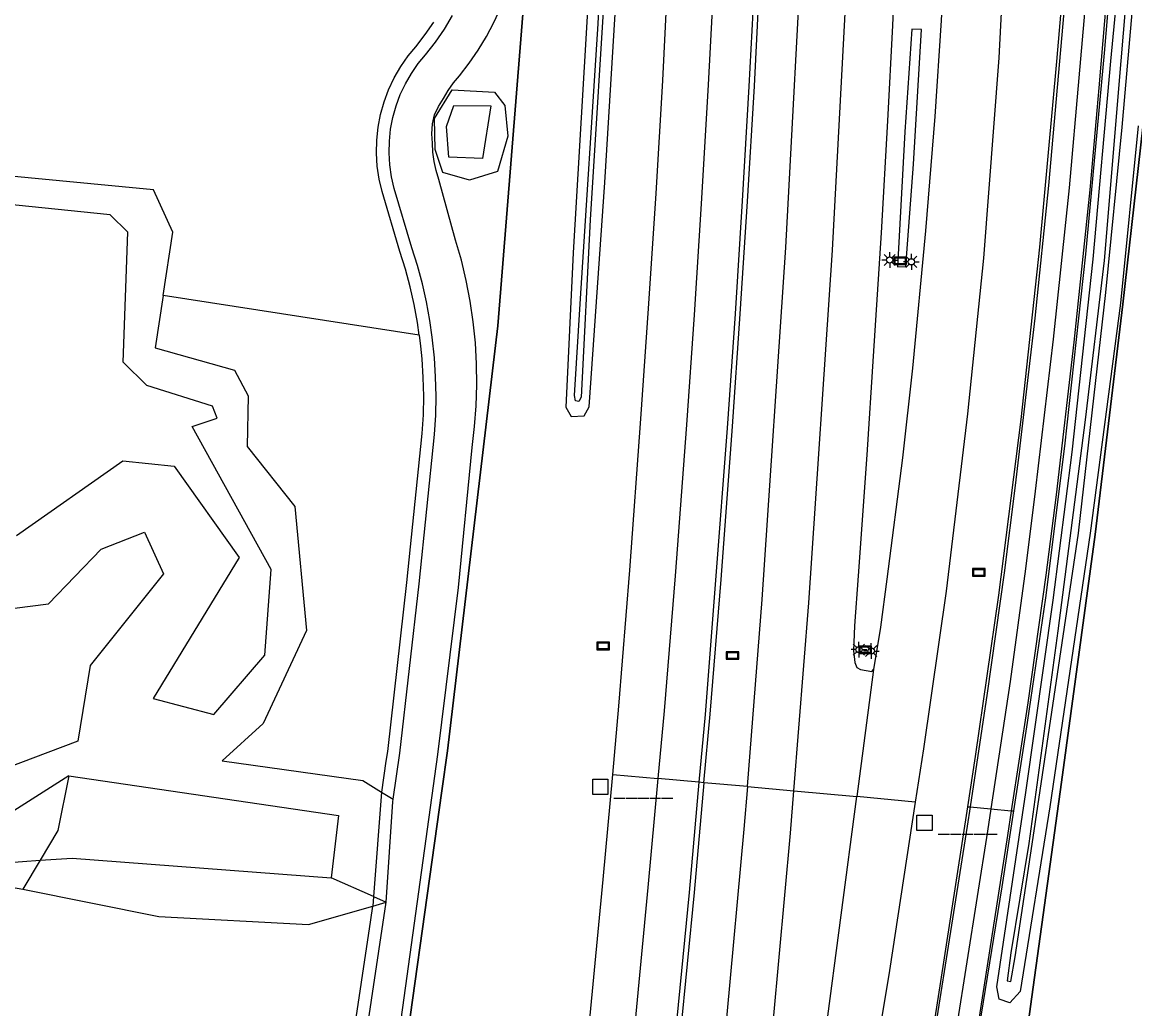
# Model space of a CAD drawing. Extents: x 124000 to 129000, y 395500 to 397503.
# Drawn here: x 124745.4 to 124833.3, y 397082 to 397160 of the extents above; entities that cross this region are included whole.
import ezdxf

# ---------------------------------------------------------------- set-up
doc = ezdxf.new("R2010")
doc.units = 0
for name, color, linetype in [('gg-afsc-hekwerk', 7, 'Continuous'), ('gg-afsc-lijn draadraster', 7, 'Continuous'), ('gg-knt-BGT kruinlijn', 7, 'Continuous'), ('gt-symb-bord', 7, 'Continuous'), ('gt-symb-hm paal', 7, 'Continuous'), ('gt-symb-lichtmast', 7, 'Continuous'), ('gx-grn-maaiveld', 7, 'Continuous'), ('gx-knt-lijn weginrichtingselement', 7, 'Continuous')]:
    doc.layers.add(name, color=color, linetype=linetype)

# ---------------------------------------------------------------- blocks, each defined once
blk = doc.blocks.new('gt0-LMAST')
at = {"layer": 'gt-symb-lichtmast'}
for p, q in [((-0.182, 0.173), (-0.447, 0.438)), ((-0.005, 0.246), (-0.005, 0.621)), ((0.172, 0.173), (0.437, 0.438)), ((-0.255, -0.004), (-0.63, -0.004)), ((-0.182, -0.181), (-0.447, -0.446)), ((-0.005, -0.254), (-0.005, -0.629)), ((0.437, -0.446), (0.172, -0.181)), ((0.245, -0.004), (0.62, -0.004))]:
    blk.add_line(p, q, dxfattribs=at)
blk.add_circle((-0.005, -0.004), 0.25, dxfattribs=at)
blk = doc.blocks.new('gt0-BORD')
at = {"layer": 'gt-symb-bord'}
blk.add_lwpolyline([(-0.5, 0.295), (-0.5, -0.295), (0.5, -0.295), (0.5, 0.295), (-0.5, 0.295)], dxfattribs=at)
blk.add_lwpolyline([(-0.417, -0.212), (0.417, -0.212), (0.417, 0.212), (-0.417, 0.212)], close=True, dxfattribs=at)
blk = doc.blocks.new('gt0-HMpaal')
at = {"layer": 'gt-symb-hm paal'}
blk.add_lwpolyline([(-0.6, 0.6), (0.6, 0.6), (0.6, -0.6), (-0.6, -0.6)], close=True, dxfattribs=at)

msp = doc.modelspace()

# ---------------------------------------------------------------- linework, layer by layer
at = {"layer": 'gg-afsc-hekwerk'}
msp.add_lwpolyline([(124774.888, 397073.073), (124778.544, 397099.23), (124778.986, 397102.392), (124782.98, 397135.974), (124785.856, 397172.14), (124786.014, 397176.607), (124786.937, 397202.711), (124786.926, 397202.713)], dxfattribs=at)
at = {"layer": 'gg-afsc-lijn draadraster'}
msp.add_lwpolyline([(124806.405, 396965.973), (124807.335, 396969.412), (124808.989, 396979.432), (124811.541, 396988.417), (124811.994, 396991.283), (124813.537, 397011.922), (124813.939, 397015.191), (124815.384, 397023.619), (124817.934, 397036.261), (124821.713, 397057.651), (124825.282, 397083.699), (124827.525, 397099.919), (124830.191, 397119.501), (124832.372, 397137.687), (124833.964, 397151.688), (124836.568, 397176.956), (124838.395, 397194.423), (124838.707, 397197.692), (124840.261, 397199.952), (124842.494, 397201.743), (124845.121, 397203.557)], dxfattribs=at)
at = {"layer": 'gg-knt-BGT kruinlijn'}
for points in [[(124778.903, 397151.737), (124779.491, 397153.393), (124782.421, 397153.375), (124781.757, 397149.224), (124779.097, 397149.322), (124778.903, 397151.737)], [(124744.924, 397119.419), (124753.314, 397125.315), (124757.368, 397124.89), (124762.522, 397117.659), (124755.71, 397106.526), (124760.526, 397105.247), (124764.547, 397109.949), (124765.048, 397116.721), (124758.802, 397128.017), (124760.777, 397128.684), (124760.398, 397129.646), (124755.217, 397131.259), (124753.355, 397133.107), (124753.704, 397143.398), (124752.323, 397144.765), (124716.543, 397148.426)], [(124749.055, 397100.408), (124740.416, 397094.931)], [(124749.055, 397100.408), (124770.372, 397097.279), (124769.797, 397092.335)], [(124743.978, 397093.541), (124746.781, 397093.736)], [(124746.781, 397093.736), (124749.302, 397093.911), (124769.797, 397092.335)]]:
    msp.add_lwpolyline(points, dxfattribs=at)
at = {"layer": 'gx-grn-maaiveld'}
for p, q in [((124776.747, 397135.256), (124756.508, 397138.384)), ((124812.673, 397108.826), (124811.345, 397098.762)), ((124792.053, 397100.524), (124795.627, 397100.198)), ((124802.693, 397099.552), (124799.258, 397099.866)), ((124802.693, 397099.552), (124806.378, 397099.216)), ((124773.769, 397099.127), (124773.138, 397090.86)), ((124773.769, 397099.127), (124774.696, 397098.554)), ((124798.208, 396999.217), (124811.345, 397098.762)), ((124806.378, 397099.216), (124811.345, 397098.762)), ((124815.973, 397098.339), (124811.345, 397098.762)), ((124746.781, 397093.736), (124745.405, 397091.435)), ((124773.138, 397090.86), (124769.797, 397092.335)), ((124773.138, 397090.86), (124773.081, 397090.108)), ((124773.138, 397090.86), (124774.15, 397090.414)), ((124773.081, 397090.108), (124774.15, 397090.414))]:
    msp.add_line(p, q, dxfattribs=at)
for points in [[(124786.937, 397202.711), (124786.014, 397176.607), (124785.856, 397172.14), (124782.98, 397135.974), (124778.986, 397102.392), (124778.544, 397099.23), (124774.888, 397073.073)], [(124792.493, 397164.558), (124793.336, 397186.577), (124793.792, 397198.942), (124793.076, 397200.057), (124792.365, 397199.989), (124791.803, 397198.95), (124791.169, 397184.399), (124790.651, 397171.158), (124788.93, 397141.752), (124788.332, 397129.544), (124788.772, 397128.809), (124789.791, 397128.882), (124790.18, 397129.594), (124791.418, 397147.308), (124792.493, 397164.558)], [(124792.053, 397100.524), (124792.546, 397105.919), (124793.395, 397116.661), (124794.283, 397128.623), (124794.888, 397137.357), (124795.489, 397146.444), (124796.008, 397155.393), (124796.758, 397170.354), (124797.147, 397179.258), (124797.715, 397194.281), (124797.844, 397199.75)], [(124801.477, 397199.665), (124801.186, 397190.886), (124800.743, 397178.945), (124800.219, 397166.983), (124799.608, 397155.046), (124799.03, 397145.628), (124798.481, 397136.86), (124797.88, 397128.167), (124796.99, 397116.232), (124796.117, 397105.554), (124795.627, 397100.198)], [(124840.261, 397199.952), (124838.707, 397197.692), (124838.395, 397194.423), (124836.568, 397176.956), (124833.964, 397151.688), (124832.372, 397137.687), (124830.191, 397119.501), (124827.525, 397099.919), (124825.282, 397083.699), (124821.713, 397057.651), (124817.934, 397036.261), (124815.384, 397023.619), (124813.939, 397015.191), (124813.537, 397011.922), (124811.994, 396991.283), (124811.541, 396988.417), (124808.989, 396979.432), (124807.335, 396969.412), (124806.405, 396965.973)], [(124799.258, 397099.866), (124799.742, 397105.283), (124800.619, 397115.925), (124801.525, 397128.032), (124802.127, 397136.933), (124802.696, 397145.813), (124803.25, 397154.939), (124803.826, 397166.677), (124804.372, 397178.604), (124804.856, 397191.558), (124805.175, 397199.578)], [(124802.693, 397099.552), (124803.862, 397114.352), (124805.745, 397142.189), (124807.181, 397169.292), (124807.714, 397182.987), (124808.133, 397199.508)], [(124806.378, 397099.216), (124807.552, 397114.081), (124809.438, 397141.966), (124810.877, 397169.122), (124811.412, 397182.868), (124811.832, 397199.421)], [(124815.623, 397199.331), (124815.376, 397190.733), (124815.034, 397180.336), (124814.576, 397168.863), (124814.158, 397159.742), (124813.763, 397152.182), (124813.263, 397143.33), (124812.64, 397133.59), (124812.135, 397125.781), (124811.451, 397116.218), (124811.177, 397112.27), (124811.095, 397110.289), (124811.191, 397109.366), (124811.339, 397108.98), (124811.631, 397108.819), (124812.527, 397108.655), (124812.673, 397108.826)], [(124819.55, 397199.157), (124819.322, 397191.497), (124818.937, 397180.542), (124818.477, 397169.025), (124818.007, 397160.137), (124817.508, 397152.544), (124816.784, 397143.505), (124815.742, 397132.649), (124814.96, 397125.558), (124813.712, 397115.965), (124813.219, 397112.169), (124812.673, 397108.826)], [(124824.71, 397198.93), (124824.187, 397190.79), (124823.99, 397188.358), (124823.72, 397182.019), (124823.602, 397178.867), (124823.421, 397173.546), (124822.568, 397157.186), (124821.361, 397141.341), (124820.11, 397129.03), (124818.402, 397115.016), (124816.619, 397102.542), (124815.973, 397098.339)], [(124789.1, 397130.056), (124789.023, 397130.472), (124789.492, 397138.147), (124790.89, 397159.871), (124791.91, 397181.556), (124792.468, 397198.573), (124792.58, 397198.74), (124792.94, 397198.725), (124792.971, 397198.565), (124792.516, 397187.236), (124791.565, 397165.104), (124790.277, 397144.363), (124789.555, 397130.34), (124789.384, 397130.014), (124789.1, 397130.056)], [(124833.592, 397151.797), (124832.183, 397137.766), (124829.788, 397119.595), (124826.61, 397097.963), (124824.265, 397083.356), (124823.459, 397082.467), (124822.605, 397082.75), (124822.412, 397083.719), (124824.719, 397099.103), (124826.864, 397114.299), (124828.375, 397125.994), (124830.027, 397141.258), (124831.424, 397156.915), (124832.636, 397169.565), (124833.27, 397179.301), (124833.609, 397187.707)], [(124834.102, 397179.257), (124833.288, 397169.452), (124832.217, 397156.933), (124830.916, 397141.146), (124829.393, 397128.559), (124827.243, 397111.868), (124824.942, 397095.048), (124823.525, 397086.424), (124823.233, 397084.201), (124823.531, 397084.16), (124823.858, 397086.09), (124825.298, 397095.537), (124828.888, 397119.593), (124831.026, 397138.621), (124832.319, 397151.689), (124834.465, 397176.119)], [(124820.123, 397097.96), (124820.735, 397101.935), (124822.587, 397114.679), (124824.332, 397128.574), (124825.822, 397142.192), (124827.162, 397156.872), (124828.552, 397173.108), (124828.661, 397173.125)], [(124832.203, 397172.797), (124830.9, 397157.533), (124829.438, 397141.65), (124827.763, 397126.481), (124826.261, 397114.488), (124824.827, 397104.624), (124823.741, 397097.63)], [(124764.09, 397000), (124778.234, 397102.088), (124779.848, 397115.306), (124780.934, 397126.377), (124781.133, 397128.016), (124781.259, 397129.67), (124781.312, 397131.328), (124781.29, 397132.987), (124781.195, 397134.643), (124781.026, 397136.294), (124780.784, 397137.935), (124780.469, 397139.564), (124780.082, 397141.177), (124779.625, 397142.765), (124778.31, 397147.551), (124778.08, 397148.267), (124777.922, 397148.98), (124777.83, 397149.705), (124777.805, 397150.434), (124777.746, 397151.16), (124777.799, 397151.946), (124777.972, 397152.679), (124778.266, 397153.319), (124778.67, 397153.95), (124779.031, 397154.585), (124779.449, 397155.184), (124779.934, 397155.759), (124780.697, 397156.747), (124781.408, 397157.783), (124782.059, 397158.856), (124782.649, 397159.965), (124783.176, 397161.104)], [(124774.696, 397098.554), (124775.225, 397102.205), (124776.739, 397115.581), (124777.964, 397127.404), (124778.053, 397128.914), (124778.082, 397130.427), (124778.049, 397131.94), (124777.955, 397133.45), (124777.78, 397135.096), (124777.59, 397136.419), (124777.323, 397137.872), (124776.999, 397139.314), (124776.618, 397140.742), (124776.178, 397142.163), (124774.776, 397146.855), (124774.563, 397147.771), (124774.427, 397148.707), (124774.369, 397149.651), (124774.39, 397150.597), (124774.49, 397151.538), (124774.668, 397152.467), (124774.923, 397153.378), (124775.254, 397154.265), (124775.657, 397155.12), (124776.13, 397155.94), (124776.67, 397156.717), (124777.253, 397157.423), (124778.035, 397158.419), (124778.747, 397159.452), (124779.394, 397160.527)], [(124776.747, 397135.256), (124776.603, 397136.258), (124776.343, 397137.672), (124776.028, 397139.075), (124775.657, 397140.465), (124775.221, 397141.872), (124773.809, 397146.598), (124773.579, 397147.586), (124773.431, 397148.604), (124773.368, 397149.631), (124773.391, 397150.661), (124773.5, 397151.685), (124773.694, 397152.696), (124773.971, 397153.688), (124774.332, 397154.654), (124774.77, 397155.584), (124775.285, 397156.476), (124775.873, 397157.322), (124776.474, 397158.05), (124777.229, 397159.012), (124777.906, 397159.994)], [(124815.824, 397148.769), (124816.463, 397159.405), (124815.693, 397159.437), (124815.145, 397151.314), (124814.554, 397140.649), (124815.215, 397140.67), (124815.824, 397148.769)], [(124779.367, 397154.656), (124782.702, 397154.46), (124783.51, 397153.401), (124783.765, 397150.992), (124782.933, 397148.193), (124780.721, 397147.494), (124778.609, 397148.114), (124778.018, 397149.924), (124777.953, 397152.379), (124779.367, 397154.656)], [(124756.508, 397138.384), (124757.281, 397143.382), (124755.753, 397146.75), (124714.145, 397150.719), (124713.144, 397146.938), (124724.981, 397126.135), (124726.593, 397115.52), (124723.363, 397095.337), (124745.405, 397091.435)], [(124756.508, 397138.384), (124755.868, 397134.247), (124762.154, 397132.469), (124763.231, 397130.46), (124763.155, 397126.456), (124766.913, 397121.689), (124767.831, 397111.907), (124764.411, 397104.535), (124761.161, 397101.603), (124772.282, 397100.044), (124773.769, 397099.127)], [(124776.747, 397135.256), (124776.758, 397135.254), (124776.85, 397134.383), (124776.958, 397133.366), (124777.05, 397131.898), (124777.082, 397130.426), (124777.054, 397128.953), (124776.967, 397127.485), (124775.745, 397115.689), (124774.233, 397102.333), (124774.123, 397101.575), (124773.769, 397099.127)], [(124739.318, 397098.181), (124733.013, 397098.227), (124736.131, 397114.763), (124739.526, 397116.345), (124742.045, 397113.312), (124747.434, 397114.012), (124751.618, 397118.325), (124755.019, 397119.678), (124756.53, 397116.376), (124750.731, 397109.143), (124749.755, 397103.155), (124742.837, 397100.541), (124739.318, 397098.181)], [(124749.055, 397100.408), (124748.188, 397096.089), (124746.781, 397093.736)], [(124788.259, 397063.214), (124788.463, 397064.56), (124789.089, 397069.716), (124790.223, 397080.902), (124791.294, 397092.21), (124792.053, 397100.524)], [(124795.627, 397100.198), (124794.838, 397091.583), (124793.772, 397080.49), (124792.634, 397069.481), (124791.058, 397055.148), (124788.546, 397035.233), (124787.385, 397026.696), (124785.077, 397010.853), (124783.594, 397001.146)], [(124799.258, 397099.866), (124798.482, 397091.187), (124797.395, 397079.909), (124796.272, 397069.2), (124794.983, 397056.083)], [(124799.258, 397099.866), (124798.867, 397099.902), (124795.627, 397100.198)], [(124802.693, 397099.552), (124802.428, 397096.193), (124801.082, 397081.526), (124800.048, 397071.094), (124798.833, 397061.54), (124798.073, 397056.813), (124798.071, 397056.035)], [(124774.15, 397090.414), (124774.665, 397098.34), (124774.696, 397098.554)], [(124794.943, 396999.648), (124795.847, 397005.844), (124801.772, 397056.513), (124802.496, 397061.013), (124803.725, 397070.678), (124804.765, 397081.174), (124806.115, 397095.878), (124806.378, 397099.216)], [(124815.973, 397098.339), (124813.926, 397085.011), (124811.533, 397070.513), (124808.364, 397048.94), (124806.611, 397034.265), (124804.942, 397021.086), (124802.75, 397005.347), (124801.107, 396998.835), (124799.874, 396993.947), (124796.296, 396979.58), (124794.601, 396971.885)], [(124815.785, 397070), (124817.946, 397083.814), (124820.123, 397097.96)], [(124823.741, 397097.63), (124822.809, 397091.63), (124819.203, 397069.379)], [(124820.123, 397097.96), (124820.302, 397097.944), (124821.939, 397097.795), (124823.553, 397097.647), (124823.741, 397097.63)], [(124745.405, 397091.435), (124756.156, 397089.285), (124767.986, 397088.65), (124773.081, 397090.108)], [(124755.338, 396725.174), (124755.247, 396729.317), (124753.621, 396750), (124751.775, 396780.891), (124750.031, 396823.955), (124749.776, 396832.987), (124749.538, 396851.815), (124750.036, 396877.691), (124751.937, 396920.062), (124756.541, 396968.751), (124756.622, 396969.603), (124757.548, 396978.144), (124760.669, 397000), (124762.21, 397010.646), (124774.15, 397090.414)], [(124761.22, 397010.789), (124763.076, 397023.187), (124772.931, 397089.025), (124773.081, 397090.108)]]:
    msp.add_lwpolyline(points, dxfattribs=at)
at = {"layer": 'gx-knt-lijn weginrichtingselement'}
for points in [[(124801.727, 397298.073), (124801.88, 397286.592), (124802.019, 397274.636), (124802.181, 397259.638), (124802.175, 397247.682), (124802.168, 397238.749), (124802.042, 397226.77), (124801.931, 397218.564), (124801.648, 397204.803), (124801.477, 397199.665), (124801.186, 397190.886), (124800.743, 397178.945), (124800.219, 397166.983), (124799.608, 397155.046), (124799.03, 397145.628), (124798.481, 397136.86), (124797.88, 397128.167), (124796.99, 397116.232), (124796.117, 397105.554), (124795.627, 397100.198), (124794.838, 397091.583), (124793.772, 397080.49), (124792.634, 397069.481)], [(124805.19, 397219.294), (124804.912, 397205.094), (124804.728, 397199.588), (124804.459, 397191.552), (124803.98, 397178.573), (124803.44, 397166.73), (124802.819, 397154.917), (124802.282, 397145.871), (124801.719, 397136.946), (124801.105, 397127.897), (124800.186, 397115.87), (124799.346, 397105.252), (124798.867, 397099.902), (124798.088, 397091.191), (124796.986, 397079.888), (124795.848, 397069.031), (124794.092, 397053.296), (124793.359, 397047.038), (124791.835, 397034.538), (124790.748, 397026.333), (124787.672, 397003.903)], [(124830.425, 397218.659), (124830.694, 397215.414), (124831.099, 397208.194), (124831.282, 397203.751), (124831.372, 397198.761), (124831.395, 397197.451), (124831.374, 397191.428), (124831.203, 397185.494), (124830.909, 397179.855), (124830.676, 397176.544), (124830.463, 397173.582), (124829.925, 397167.579), (124829.704, 397164.62), (124828.914, 397155.587), (124828.142, 397146.905), (124826.871, 397134.932), (124825.461, 397122.926), (124824.674, 397116.782), (124823.462, 397107.86), (124821.939, 397097.795), (124821.673, 397096.038), (124818.411, 397075.376), (124817.395, 397069.022)], [(124828.05, 397164.686), (124827.184, 397154.841), (124826.51, 397147.083), (124825.425, 397136.594), (124823.878, 397123.363), (124823.002, 397116.45), (124821.651, 397106.932), (124820.302, 397097.944), (124820.075, 397096.429), (124816.256, 397072.286)], [(124831.257, 397163.855), (124830.48, 397154.814), (124829.763, 397146.744), (124828.51, 397134.681), (124827.102, 397122.614), (124826.286, 397116.262), (124824.87, 397106.191), (124823.553, 397097.647), (124823.251, 397095.691), (124820.428, 397077.442)]]:
    msp.add_lwpolyline(points, dxfattribs=at)

# ---------------------------------------------------------------- block references
at = {"layer": 'gt-symb-bord'}
for p in [(124814.776, 397141.126), (124820.996, 397116.493), (124791.301, 397110.677), (124801.514, 397109.914), (124812.001, 397110.364)]:
    msp.add_blockref('gt0-BORD', p, dxfattribs=at)
at = {"layer": 'gt-symb-hm paal'}
for p in [(124791.074, 397099.534), (124816.701, 397096.695)]:
    msp.add_blockref('gt0-HMpaal', p, dxfattribs=at)
at = {"layer": 'gt-symb-lichtmast'}
for p in [(124813.953, 397141.192), (124815.665, 397141.049), (124811.52, 397110.39), (124812.494, 397110.281)]:
    msp.add_blockref('gt0-LMAST', p, dxfattribs=at)

# ---------------------------------------------------------------- texts
at = {"layer": 'gt-symb-hm paal'}
for p in [(124792.155, 397098.93), (124817.782, 397096.091)]:
    msp.add_text('_____', height=1.25, dxfattribs=at).set_placement(p)

doc.saveas('drawing.dxf')
